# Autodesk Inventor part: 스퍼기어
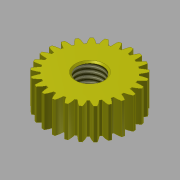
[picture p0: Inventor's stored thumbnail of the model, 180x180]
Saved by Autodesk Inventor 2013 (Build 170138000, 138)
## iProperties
Created: 2017-04
Part Number: 스퍼기어
Material: 강철
Document SubType Name: Modeling
Designer: mduedu
Categories: <?xml version="1.0" encoding="UTF-16"?> <MemberInstance><Categories><FamilyTemplate><FamilyTemplateParameter ValueType="xs:double" Id="1" ObjectReferenceKey="da
Density: 7.85 g/cm^3
Mass: 33.8546 g
Surface Area: 26.941 cm^2
Volume: 4.31269 cm^3
Author: mduedu
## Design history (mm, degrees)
sketch "Sketch1"
  geometry: C1 r 13.5 at (0, 0)
  constraints: 1 centre point
  dimensions: "d0" = 27 diameter of C1 (= da_da)
extrude "Extrusion1" new body sketch "Sketch1" distance "d1" = 10 (= da_b); taper "d2" = 0 deg
workplane "Work Plane2"
sketch "Sketch2"
  geometry: C1 r 13.5 at (0, 0) reference; C2 r 12.5 at (0, 0)
  constraints: 1 centre point, 1 coincident
  dimensions: "d3" = 25 diameter of C2 (= da_dw)
feature "피치 지름" sketch "Sketch2" dims "d4" = 10, "d5" = 0
workplane "Work Plane8"
workplane "Work Plane9"
feature "스퍼 기어" dims "da_b" = 10, "da_d" = 25, "da_aw" = 25, "da_da" = 27, "da_df" = 22.5, "da_dw" = 25, angle "da_beta" = 0 deg, "da_lefttooth" = 0, "da_righttooth" = 0
sketch "스케치3"
  geometry: C1 r 4.188 at (0, 0); 1 further point
  constraints: 1 centre point, 1 coincident
  dimensions: "d49" = 8.376 diameter of C1
extrude "돌출2" cut sketch "스케치3" stored distance "d50" = 10; taper "d51" = 0 deg
feature "스레드1" dims "d52" = 10, "d53" = 0
chamfer "모따기1" distance "d54" = 0.5; stored, may be unused: second distance "d55" = 2, angle "d56" = 45 deg
body "Solid1"
body "Srf1"
other parameters: "d16" = 25 (= da_aw), "d17" = 0, "d34" = 1.25664 (computed from da_z), "d39" = 0, "d41" = 0, "d43" = 25 (= da_aw), "d46" = 25 (= da_aw), "d47" = 0, "d48" = 0
